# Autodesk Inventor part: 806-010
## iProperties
Author: Charles Bliss
Shininess: 60.0
PropertySet Name: _Private Model Information
Created: 2001-04
Part Number: 806-010
Document SubType Name: Modeling
Designer: Charles Bliss
Material: PVC-Piping
Description: Elbow, 90 Deg, PVC 80, 1" SxS
Control State: 0
Master: False
Checked Out: False
PropertySet Name: Design Tracking Control
Density: 1.4
Volumn: 35.28225383619877
Area: 131.32150331617106
PropertySet Name: Model Information
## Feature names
1. Revolution3
2. RevFor45 [Revolution]
3. Revolution2
4. Revolution1
5. Revolution4
6. Revolution5
7. Fillet1
